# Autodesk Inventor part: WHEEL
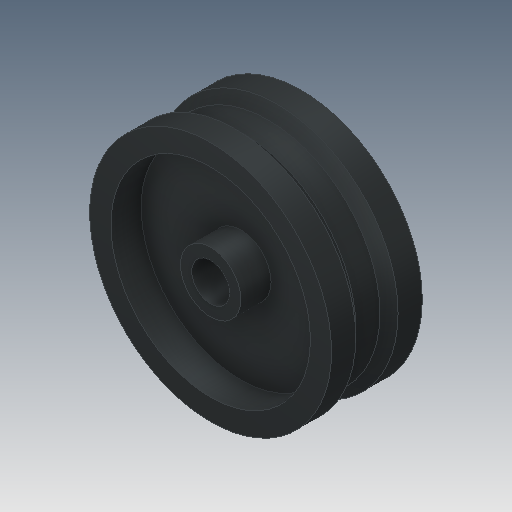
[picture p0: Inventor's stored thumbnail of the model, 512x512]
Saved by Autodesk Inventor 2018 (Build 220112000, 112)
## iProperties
Created: 2016-05
Part Number: WHEEL
Material: Iron, Cast
Document SubType Name: Modeling
Designer: CADCIM
Density: 7.15 g/cm^3
Appearance: Iron Gray
Mass: 68.7858 g
Surface Area: 60.8074 cm^2
Volume: 9.62039 cm^3
Author: CADCIM
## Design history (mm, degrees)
sketch "Sketch1"
  geometry: L1 (0, 0)-(-43, 0); L2 (-20, 3.5)-(-18.5, 2); L3 (-20, -3.5)-(-18.5, -2); L4 (-20, 7.5)-(-20, 3.5); L5 (-20, -3.5)-(-20, -7.5); L6 (-5, 7.5)-(-5, 2.5); L7 (-5, 2.5)-(-16.5, 2.5); L8 (-16.5, 2.5)-(-16.5, 7.5); L9 (-16.5, -7.5)-(-16.5, -2.5); L10 (-16.5, -2.5)-(-5, -2.5); L11 (-5, -2.5)-(-5, -7.5); L12 (-3.125, 7.5)-(-5, 7.5); L13 (-16.5, 7.5)-(-20, 7.5); L14 (-20, -7.5)-(-16.5, -7.5); L15 (-5, -7.5)-(-3.125, -7.5); L16 (0, 7.495)-(0, -7.5); L17 (-3.125, 7.5)-(-3.125, -7.5); L18 (-18.5, 2)-(-18.5, -2); 1 further point
  constraints: 36 end point, 11 perpendicular, 4 collinear, 4 parallel, 4 vertical, 3 horizontal, 2 point on line, 4 other
  dimensions: "d1" = 15 distance of L4.start L5.end; "d2" = 90 deg angle of L3 L2; "d3" = 4 distance of L2.start L4.start; "d4" = 5 distance between parallel lines of L10 L7; "d5" = 6.25 diameter of L17 L16; "d6" = 10 diameter of L11 L16; "d7" = 33 diameter of L9 L16; "d9" = 40 diameter of L4 L16; "d11" = 1.5 distance between parallel lines of L5 L18
revolve "Revolution1" sketch "Sketch1" stored, may be unused: angle "d10" = 90 deg
body "Solid1"
